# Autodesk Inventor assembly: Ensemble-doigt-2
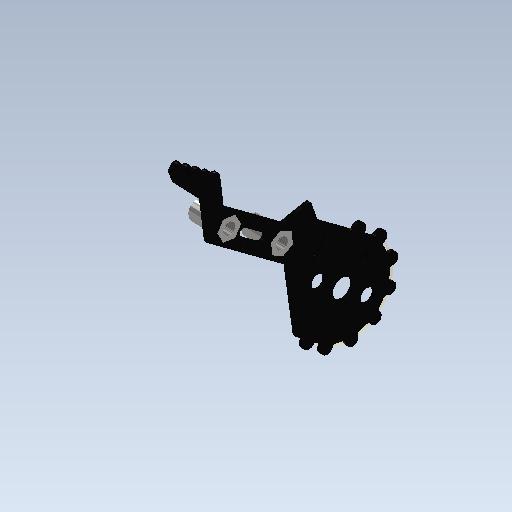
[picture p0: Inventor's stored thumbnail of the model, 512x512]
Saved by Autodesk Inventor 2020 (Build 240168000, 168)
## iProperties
Created: 2021-10
Part Number: Ensemble-doigt-2
Document SubType Name: Assembly
Designer: bruno
Author: bruno
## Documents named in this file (3)
- C:\Users\bruno\Documents\1-Cours-2021-22\1SI\Challenge-2021\Pince-Inventor\Ensemble-doigt-2.iam
- C:\Users\bruno\Documents\1-Cours-2021-22\1SI\Challenge-2021\Pince-Inventor\pince.ipt
- C:\Users\bruno\Documents\1-Cours-2021-22\1SI\Challenge-2021\Pince-Inventor\Ecrou-support.ipt
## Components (3 placed, 2 different names)
1. pince:1 — Affleurement:3, Placage:6, Placage:7, Affleurement:4, Placage:8, Placage:9
2. Ecrou-support:1 — Affleurement:3, Placage:6, Placage:7
3. Ecrou-support:2 — Affleurement:4, Placage:8, Placage:9
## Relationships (6: Mate 4, Flush 2)
- Affleurement:3 [Flush]: pince:1 ↔ Ecrou-support:1
- Placage:6 [Mate]: pince:1 ↔ Ecrou-support:1
- Placage:7 [Mate]: pince:1 ↔ Ecrou-support:1
- Affleurement:4 [Flush]: pince:1 ↔ Ecrou-support:2
- Placage:8 [Mate]: pince:1 ↔ Ecrou-support:2
- Placage:9 [Mate]: pince:1 ↔ Ecrou-support:2
